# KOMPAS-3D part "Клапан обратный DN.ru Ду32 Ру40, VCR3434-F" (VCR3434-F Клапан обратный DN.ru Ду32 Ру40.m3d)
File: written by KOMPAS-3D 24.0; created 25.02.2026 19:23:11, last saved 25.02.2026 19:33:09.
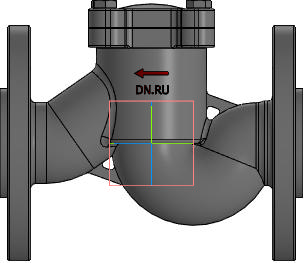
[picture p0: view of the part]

Document properties: Автор: R2D2; Полное имя файла: VCR3434-F Клапан обратный DN.ru Ду32 Ру40.cdw

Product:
- Part/product: Клапан обратный DN.ru Ду32 Ру40  | designation VCR3434-F
    Масса: 5.9
    Раздел спецификации: Прочие изделия
    Форматы листов документа: A3
    Примечание: D100-04053
    additional columns: D100-04053

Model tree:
1. Операция без истории:2

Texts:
  VCR3434-F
